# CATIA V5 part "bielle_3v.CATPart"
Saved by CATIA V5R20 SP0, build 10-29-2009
Part number: bielle_3v
Bounding box of the stored display mesh (mm): x 163.518 to 199.34, y 146.048 to 270.404, z 96.842 to 136.842
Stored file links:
  D:\ecole\thinkmotion\IAO\bielle_3v.CATPart
  D:\ecole\thinkmotion\IAO\mecanisme coulisseau.CATProduct
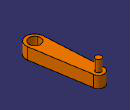
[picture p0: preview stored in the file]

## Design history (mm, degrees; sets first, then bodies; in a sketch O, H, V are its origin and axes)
External parameters (linked from other documents)
  External.rayon_pivot_bati = 10 mm
Set1
  Plane1: linked copy from another document
  Point1 to Point4: linked copy from another document
  Plane2: linked copy from another document
  Point5: linked copy from another document
  Plane3: linked copy from another document
Body1 (main body)
  Sketch1 on Plane1, origin (0, 0, 116.8423), H (1, 0, 0), V (0, -1, 0)
    arc A1 centre (184.3405, -161.0266) radius 15 from (199.1522, -163.3962) to (169.3663, -160.1482) ccw
    point P1 (184.3405, -161.0266)
    point P2 (199.1522, -163.3962)
    point P3 (169.3663, -160.1482)
    reference projected point E1 (184.3405, -161.0266) from Point2
    reference projected point E2 (185.9666, -146.115) from Point1
    arc A2 centre (173.5004, -260.4373) radius 10 from (183.3748, -262.017) to (163.5175, -259.8517) cw
    point P4 (173.5004, -260.4373)
    point P5 (183.3748, -262.017)
    point P6 (163.5175, -259.8517)
    reference projected point E3 (173.5004, -260.4373) from Point3
    reference projected point E4 (172.4164, -270.3784) from Point4
    line L1 (163.5175, -259.8517) -> (169.3663, -160.1482)
    point P7 (163.5175, -259.8517)
    point P8 (169.3663, -160.1482)
    line L2 (199.1522, -163.3962) -> (183.3748, -262.017)
    point P9 (199.1522, -163.3962)
    point P10 (183.3748, -262.017)
    coincidence: P1 E1, A1 E2, P4 E3, A2 E4, P8 P3, P7 P6, P10 P5, P9 P2
    tangency: A2 L2, L2 A1, L1 A2, L1 A1
  Pad1: profile Sketch1, direction (0, 0, -1), up to Plane2
  Sketch2 on Plane1, origin (0, 0, 116.8423), H (1, 0, 0), V (0, -1, 0)
    circle A1 centre (173.5004, -260.4373) radius 5
    point P1 (173.5004, -260.4373)
    reference projected point E1 (173.5004, -260.4373) from Point3
    reference projected point E2 (172.9584, -265.4078) from Point5
    coincidence: P1 E1, A1 E2
  Pad2: profile Sketch2, direction (0, 0, -1), up to Plane3
  Sketch3 on Plane1, origin (0, 0, 116.8423), H (1, 0, 0), V (0, -1, 0)
    point P1 (184.3405, -161.0266)
    reference projected point E1 (184.3405, -161.0266) from Point2
    coincidence: E1 P1
  Hole1: placed by Sketch3, at (184.3405, 161.0266, 116.8423) direction (0, 0, 1), diameter 20 {= External.rayon_pivot_bati *2}, up to Plane2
